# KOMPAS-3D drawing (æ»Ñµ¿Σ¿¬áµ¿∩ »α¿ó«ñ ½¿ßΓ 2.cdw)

Referenced files: 2.cdw
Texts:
  ПЛК.303341.01 СП
  Назаров
  Шайба 6 Л ГОСТ 6402-70
  Шайба пружинная
  Шайба
  ГОСТ
  Сборочный чертеж
  Шайбы ГОСТ 6402-70
  ПШП. РЧО.140.00.00 СБ-
Dimensions and other numbers on the sheet: 65Г; 029; 70; 1:1; 1; 2; 12 ЛБрКМц3-1; 13; 8 ЛБрКМц3-1; 4; 11; 12; 16 ЛБрКМц3-1; 0; 3; 5; 6; 7; 8; 9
